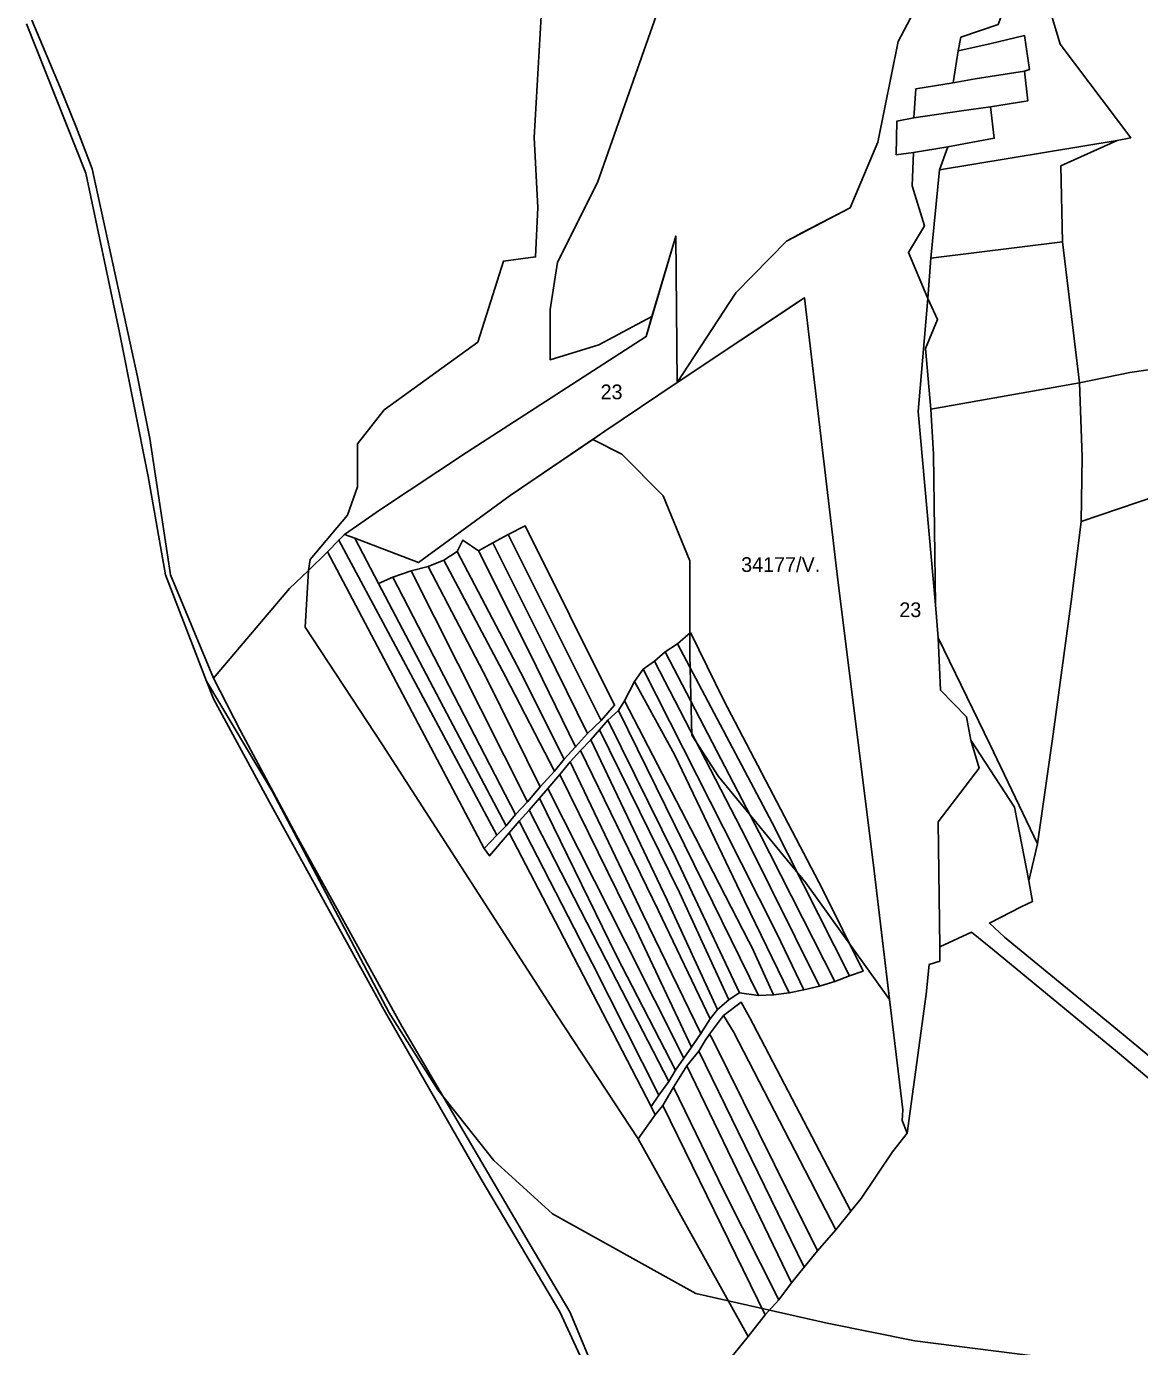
# Model space of a CAD drawing. Extents: x -532083 to -529270, y -1180561 to -1176456.
# Drawn here: x -531324.4 to -530947.6, y -1179426.9 to -1178980.2 of the extents above; entities that cross this region are included whole.
import ezdxf

# ---------------------------------------------------------------- set-up
doc = ezdxf.new("R2010")
doc.units = 0
for name, color, linetype in [('95560013', 7, 'Continuous'), ('95590013', 7, 'Continuous'), ('95610013', 7, 'Continuous'), ('95620013', 7, 'Continuous'), ('95660013', 7, 'Continuous')]:
    doc.layers.add(name, color=color, linetype=linetype)

msp = doc.modelspace()

# ---------------------------------------------------------------- linework, layer by layer
at = {"layer": '95560013'}
for points in [[(-530658.2913, -1178954.87545), (-530725.8063, -1179044.23145), (-530751.3463, -1179049.30845), (-530752.6093, -1179042.71945), (-530853.6623, -1179066.28845), (-530855.4313, -1179080.22645), (-530874.6313, -1179084.02845), (-530909.1583, -1179091.26445), (-530950.9083, -1179097.29245), (-530967.9883, -1179100.78345), (-530973.6643, -1179053.04545), (-530974.3083, -1179027.41445), (-530955.1983, -1179018.79845), (-530950.6093, -1179017.85245), (-530974.5343, -1178986.22345), (-530983.6223, -1178955.52445)], [(-531150.1463, -1178976.77445), (-531152.5333, -1179017.82345), (-531151.3393, -1179041.42645), (-531152.0213, -1179058.18745), (-531162.9583, -1179059.58045), (-531171.5883, -1179086.99245), (-531203.2613, -1179109.97745), (-531212.3343, -1179121.40645), (-531212.3343, -1179136.00945), (-531215.7103, -1179145.53345), (-531228.3693, -1179160.55945), (-531228.8523, -1179164.29845), (-531235.3893, -1179170.37045), (-531261.0553, -1179200.73045), (-531275.5833, -1179165.75645), (-531282.6483, -1179119.64545), (-531286.8093, -1179098.77645), (-531302.1293, -1179028.39245), (-531307.4333, -1179014.46145), (-531313.0023, -1179000.91345), (-531322.5833, -1178978.13445)], [(-530929.8263, -1179340.76445), (-530953.2153, -1179321.37245), (-530993.3103, -1179288.33545), (-530998.4563, -1179283.64445), (-530987.6603, -1179278.10345), (-530983.8933, -1179276.34045), (-530985.1493, -1179269.28745), (-530982.2213, -1179256.82645), (-530976.8443, -1179219.70345), (-530970.5183, -1179173.06145), (-530967.3553, -1179147.74245), (-530884.2313, -1179119.50845)], [(-531116.1203, -1179467.89045), (-531080.0903, -1179423.57845), (-531074.3173, -1179416.15945), (-531069.7743, -1179411.12345), (-531065.4713, -1179405.36745), (-531061.1673, -1179400.09145), (-531056.6253, -1179394.57545), (-531050.4083, -1179387.38045), (-531045.3873, -1179381.14545), (-531041.8013, -1179376.82845), (-531031.2813, -1179360.99945), (-531026.2603, -1179354.76445), (-531019.8023, -1179307.72745), (-531018.8473, -1179297.67245), (-531015.2683, -1179296.47545), (-531015.2793, -1179291.70545), (-531004.4833, -1179286.66745), (-530997.3683, -1179292.40545), (-530955.1243, -1179327.35845), (-530904.5683, -1179369.77645), (-530923.8833, -1179413.83845), (-530953.9483, -1179487.19045)]]:
    msp.add_lwpolyline(points, dxfattribs=at)
for points in [[(-531019.2943, -1179072.28945), (-531025.8403, -1179056.70745), (-531020.4723, -1179047.66145), (-531024.5523, -1179034.09145), (-531024.1223, -1179022.89045), (-531012.5273, -1179020.95245), (-531015.3193, -1179028.70645), (-531018.3253, -1179058.64645)], [(-531018.2783, -1179109.66745), (-531020.0433, -1179089.23245), (-531015.9633, -1179079.32345), (-531019.2943, -1179072.28945), (-531018.3253, -1179058.64645), (-530973.6643, -1179053.04545), (-530967.9883, -1179100.78345)], [(-530884.2313, -1179119.50845), (-530967.3553, -1179147.74245), (-530967.0393, -1179125.84945), (-530967.9883, -1179100.78345), (-530950.9083, -1179097.29245), (-530909.1583, -1179091.26445), (-530874.6313, -1179084.02845), (-530875.3893, -1179085.80245), (-530885.7473, -1179102.27545), (-530860.2313, -1179130.15245), (-530857.4993, -1179133.02145), (-530831.6833, -1179099.23445), (-530851.1363, -1179133.70045), (-530860.4833, -1179136.74145), (-530875.3893, -1179122.80345)], [(-531165.1163, -1179253.85345), (-531194.3713, -1179199.25245), (-531218.6643, -1179153.99845), (-531216.7653, -1179152.09445), (-531213.1783, -1179153.36345), (-531205.1623, -1179168.70445), (-531180.9433, -1179214.88745), (-531161.9993, -1179250.72645)], [(-531169.4333, -1179258.42345), (-531222.4623, -1179158.02045), (-531218.6643, -1179153.99845), (-531194.3713, -1179199.25245), (-531165.1163, -1179253.85345)], [(-531117.2793, -1179356.63845), (-531144.6613, -1179315.17945), (-531203.9123, -1179223.31745), (-531230.0623, -1179183.48645), (-531228.8523, -1179164.29845), (-531222.4623, -1179158.02045), (-531169.4333, -1179258.42345), (-531167.6543, -1179260.89745), (-531160.9723, -1179253.13645), (-531143.9163, -1179285.76645), (-531112.9723, -1179345.70745), (-531111.6153, -1179348.52845)], [(-531116.1203, -1179467.89045), (-531124.8823, -1179452.54945), (-531140.4943, -1179415.15645), (-531154.1953, -1179391.98545), (-531197.3323, -1179318.53245), (-531232.9843, -1179254.01545), (-531251.9673, -1179218.60745), (-531261.0553, -1179200.73045), (-531235.3893, -1179170.37045), (-531228.8523, -1179164.29845), (-531230.0623, -1179183.48645), (-531203.9123, -1179223.31745), (-531144.6613, -1179315.17945), (-531117.2793, -1179356.63845), (-531080.0903, -1179423.57845)], [(-531161.9993, -1179250.72645), (-531180.9433, -1179214.88745), (-531205.1623, -1179168.70445), (-531200.3663, -1179166.54045), (-531158.8823, -1179246.87745)], [(-531079.8783, -1179289.81545), (-531097.8853, -1179254.72745), (-531121.9943, -1179208.45245), (-531118.5393, -1179201.88645), (-531104.9123, -1179226.75245), (-531081.4163, -1179275.87345), (-531066.1913, -1179307.25045), (-531071.4673, -1179307.95545), (-531078.7813, -1179291.95345)], [(-531079.8783, -1179289.81545), (-531078.7813, -1179291.95345), (-531071.4673, -1179307.95545), (-531076.5673, -1179308.13245), (-531092.1063, -1179276.65345), (-531123.9943, -1179211.73545), (-531121.9943, -1179208.45245), (-531097.8853, -1179254.72745)], [(-531083.0753, -1179307.25045), (-531104.6933, -1179261.33545), (-531127.6423, -1179214.90245), (-531123.9943, -1179211.73545), (-531092.1063, -1179276.65345), (-531076.5673, -1179308.13245)], [(-531106.9923, -1179337.23945), (-531128.1893, -1179296.22645), (-531154.1943, -1179245.38045), (-531150.7603, -1179241.40545), (-531124.6753, -1179294.68445), (-531104.7063, -1179333.35845)], [(-531112.9723, -1179345.70745), (-531143.9163, -1179285.76645), (-531160.9723, -1179253.13645), (-531157.6293, -1179249.09145), (-531132.8003, -1179297.41545), (-531110.3343, -1179341.82645)], [(-531056.6253, -1179394.57545), (-531071.2093, -1179365.31645), (-531092.2493, -1179322.62745), (-531093.2053, -1179321.18845), (-531088.4233, -1179314.95345), (-531085.0763, -1179320.46945), (-531050.4083, -1179387.38045)], [(-531065.4713, -1179405.36745), (-531100.8563, -1179331.98045), (-531096.7913, -1179326.94445), (-531061.1673, -1179400.09145)], [(-531069.7743, -1179411.12345), (-531088.1843, -1179374.43045), (-531105.3983, -1179339.17545), (-531100.8563, -1179331.98045), (-531065.4713, -1179405.36745)], [(-531080.0903, -1179423.57845), (-531117.2793, -1179356.63845), (-531111.6153, -1179348.52845), (-531108.9853, -1179345.41145), (-531074.3173, -1179416.15945)]]:
    msp.add_lwpolyline(points, close=True, dxfattribs=at)
at = {"layer": '95590013'}
for points in [[(-530986.5903, -1178995.34045), (-531003.2823, -1178997.94445), (-531010.7013, -1178999.24745), (-531009.0323, -1178988.45645), (-530998.2743, -1178986.03745), (-530986.5903, -1178983.24645), (-530984.9213, -1178994.78145)], [(-530998.0893, -1179007.43345), (-531007.9193, -1179008.73645), (-531024.0553, -1179011.15445), (-531023.3133, -1179001.29345), (-531010.7013, -1178999.24745), (-531003.2823, -1178997.94445), (-530986.5903, -1178995.34045), (-530985.4773, -1179005.38745)], [(-530996.7913, -1179018.03845), (-531012.5273, -1179020.95245), (-531024.1223, -1179022.89045), (-531029.9903, -1179023.62045), (-531029.8043, -1179012.27145), (-531024.0553, -1179011.15445), (-531007.9193, -1179008.73645), (-530998.0893, -1179007.43345)], [(-531134.4233, -1179219.45745), (-531148.5713, -1179190.83345), (-531166.5553, -1179154.99445), (-531161.2803, -1179152.10845), (-531129.8673, -1179215.12745)], [(-531129.8673, -1179215.12745), (-531161.2803, -1179152.10845), (-531155.5253, -1179149.22145), (-531125.3113, -1179209.83545)], [(-531142.3363, -1179228.11645), (-531157.2033, -1179198.77145), (-531178.5453, -1179157.88045), (-531176.6263, -1179154.03245), (-531171.3513, -1179157.64045), (-531154.0863, -1179192.03645), (-531138.5003, -1179224.02745)], [(-531138.5003, -1179224.02745), (-531154.0863, -1179192.03645), (-531171.3513, -1179157.64045), (-531166.5553, -1179154.99445), (-531148.5713, -1179190.83345), (-531134.4233, -1179219.45745)], [(-531150.4893, -1179237.49745), (-531168.4733, -1179201.17645), (-531188.3763, -1179162.93245), (-531183.1013, -1179160.76745), (-531162.2393, -1179200.21445), (-531145.6933, -1179232.20545)], [(-531145.6933, -1179232.20545), (-531162.2393, -1179200.21445), (-531183.1013, -1179160.76745), (-531178.5453, -1179157.88045), (-531157.2033, -1179198.77145), (-531142.3363, -1179228.11645)], [(-531154.8053, -1179242.54845), (-531194.1313, -1179164.37545), (-531188.3763, -1179162.93245), (-531168.4733, -1179201.17645), (-531150.4893, -1179237.49745)], [(-530989.9193, -1179244.35145), (-531004.7343, -1179221.68245), (-531006.2403, -1179213.87345), (-531015.0283, -1179204.80645), (-531015.7483, -1179187.08645), (-530998.3523, -1179223.06645), (-530982.2213, -1179256.82645), (-530985.1493, -1179269.28745)], [(-531080.7573, -1179254.94745), (-531111.8113, -1179194.95445), (-531108.1743, -1179191.85445), (-531076.3653, -1179252.96545), (-531050.7153, -1179303.36945), (-531055.9913, -1179304.95645)], [(-531088.4433, -1179251.42345), (-531115.6303, -1179197.69145), (-531111.8113, -1179194.95445), (-531080.7573, -1179254.94745), (-531055.9913, -1179304.95645), (-531061.2673, -1179306.19145), (-531070.4363, -1179287.10745)], [(-531103.3753, -1179273.23045), (-531130.4163, -1179218.21545), (-531127.6423, -1179214.90245), (-531104.6933, -1179261.33545), (-531083.0753, -1179307.25045), (-531084.1303, -1179307.95545), (-531086.5923, -1179309.54345)], [(-531107.5473, -1179275.87345), (-531133.3223, -1179221.66145), (-531130.4163, -1179218.21545), (-531103.3753, -1179273.23045), (-531086.5923, -1179309.54345), (-531090.4613, -1179312.89545)], [(-531115.6723, -1179280.80745), (-531140.3243, -1179229.08145), (-531136.8893, -1179225.23845), (-531110.4023, -1179279.48545), (-531092.9233, -1179316.07045), (-531096.0893, -1179321.00945)], [(-531117.8683, -1179286.09345), (-531143.8903, -1179233.32245), (-531140.3243, -1179229.08145), (-531115.6723, -1179280.80745), (-531096.0893, -1179321.00945), (-531099.2543, -1179325.59645)], [(-531121.6013, -1179290.05845), (-531147.8533, -1179238.09245), (-531143.8903, -1179233.32245), (-531117.8683, -1179286.09345), (-531099.2543, -1179325.59645), (-531101.8923, -1179329.30145)], [(-531124.6753, -1179294.68445), (-531150.7603, -1179241.40545), (-531147.8533, -1179238.09245), (-531121.6013, -1179290.05845), (-531101.8923, -1179329.30145), (-531104.7063, -1179333.35845)], [(-531132.8003, -1179297.41545), (-531157.6293, -1179249.09145), (-531154.1943, -1179245.38045), (-531128.1893, -1179296.22645), (-531106.9923, -1179337.23945), (-531110.3343, -1179341.82645)], [(-531050.4083, -1179387.38045), (-531085.0763, -1179320.46945), (-531088.4233, -1179314.95345), (-531082.4463, -1179310.39645), (-531079.5773, -1179315.67245), (-531078.3813, -1179317.83145), (-531045.3873, -1179381.14545)], [(-531074.3173, -1179416.15945), (-531108.9853, -1179345.41145), (-531105.3983, -1179339.17545), (-531088.1843, -1179374.43045), (-531069.7743, -1179411.12345)]]:
    msp.add_lwpolyline(points, close=True, dxfattribs=at)
at = {"layer": '95610013'}
for points in [[(-530986.5903, -1178983.24645), (-530998.2743, -1178986.03745), (-531009.0323, -1178988.45645), (-531008.1043, -1178983.80445), (-530995.4923, -1178979.52545), (-530991.7833, -1178969.47845), (-530986.2193, -1178966.50145), (-530988.6303, -1178960.91945), (-530990.8563, -1178955.71045), (-530986.5903, -1178955.52445), (-530983.6223, -1178955.52445), (-530974.5343, -1178986.22345), (-530950.6093, -1179017.85245), (-530955.1983, -1179018.79845), (-531015.3193, -1179028.70645), (-531012.5273, -1179020.95245), (-530996.7913, -1179018.03845), (-530998.0893, -1179007.43345), (-530985.4773, -1179005.38745), (-530986.5903, -1178995.34045), (-530984.9213, -1178994.78145)], [(-530973.6643, -1179053.04545), (-531018.3253, -1179058.64645), (-531015.3193, -1179028.70645), (-530955.1983, -1179018.79845), (-530974.3083, -1179027.41445)], [(-531158.8823, -1179246.87745), (-531200.3663, -1179166.54045), (-531194.1313, -1179164.37545), (-531154.8053, -1179242.54845)], [(-531071.9733, -1179249.66145), (-531103.9923, -1179189.11845), (-531099.6283, -1179185.28745), (-531088.3533, -1179208.27045), (-531054.9363, -1179272.14445), (-531041.2183, -1179299.84045), (-531045.7913, -1179301.42845)], [(-531076.3653, -1179252.96545), (-531108.1743, -1179191.85445), (-531103.9923, -1179189.11845), (-531071.9733, -1179249.66145), (-531045.7913, -1179301.42845), (-531050.7153, -1179303.36945)], [(-531081.4163, -1179275.87345), (-531104.9123, -1179226.75245), (-531118.5393, -1179201.88645), (-531115.6303, -1179197.69145), (-531088.4433, -1179251.42345), (-531070.4363, -1179287.10745), (-531061.2673, -1179306.19145), (-531066.1913, -1179307.25045)], [(-531110.4023, -1179279.48545), (-531136.8893, -1179225.23845), (-531133.3223, -1179221.66145), (-531107.5473, -1179275.87345), (-531090.4613, -1179312.89545), (-531092.9233, -1179316.07045)], [(-531061.1673, -1179400.09145), (-531096.7913, -1179326.94445), (-531094.6393, -1179323.34745), (-531093.2053, -1179321.18845), (-531092.2493, -1179322.62745), (-531071.2093, -1179365.31645), (-531056.6253, -1179394.57545)]]:
    msp.add_lwpolyline(points, close=True, dxfattribs=at)
at = {"layer": '95620013'}
msp.add_lwpolyline([(-530995.4923, -1178979.52545), (-531008.1043, -1178983.80445), (-531009.0323, -1178988.45645), (-531010.7013, -1178999.24745), (-531023.3133, -1179001.29345), (-531024.0553, -1179011.15445), (-531029.8043, -1179012.27145), (-531029.9903, -1179023.62045), (-531024.1223, -1179022.89045), (-531024.5523, -1179034.09145), (-531020.4723, -1179047.66145), (-531025.8403, -1179056.70745), (-531019.2943, -1179072.28945), (-531015.9633, -1179079.32345), (-531020.0433, -1179089.23245), (-531018.2783, -1179109.66745), (-531017.3293, -1179124.89745), (-531016.6973, -1179175.98045), (-531015.7483, -1179187.08645), (-531015.0283, -1179204.80645), (-531006.2403, -1179213.87345), (-531004.7343, -1179221.68245), (-531001.9723, -1179231.25345), (-531015.7823, -1179249.38945), (-531015.2793, -1179291.70545), (-531015.2683, -1179296.47545), (-531018.8473, -1179297.67245), (-531019.8023, -1179307.72745), (-531026.2603, -1179354.76445), (-531027.9343, -1179350.44745), (-531027.6953, -1179346.85045), (-531031.5953, -1179315.04845), (-531037.8153, -1179263.12745), (-531049.4773, -1179169.35045), (-531061.0463, -1179072.00045), (-531104.0743, -1179100.66545), (-531084.2413, -1179070.40245), (-531067.1513, -1179052.83645), (-531045.6303, -1179041.61945), (-531036.2273, -1179019.31245), (-531029.3253, -1178985.34245), (-531009.6953, -1178948.12645)], dxfattribs=at)
msp.add_lwpolyline([(-531128.5713, -1179117.17345), (-531160.6413, -1179138.97245), (-531191.6573, -1179161.61745), (-531213.1783, -1179153.36345), (-531216.7653, -1179152.09445), (-531204.5273, -1179143.62845), (-531175.4113, -1179124.36945), (-531114.6723, -1179085.13745), (-531104.6033, -1179051.12945), (-531104.0743, -1179100.66545)], close=True, dxfattribs=at)
at = {"layer": '95660013'}
for points in [[(-531009.6953, -1178948.12645), (-531029.3253, -1178985.34245), (-531036.2273, -1179019.31245), (-531045.6303, -1179041.61945), (-531062.1193, -1179050.21345), (-531065.2463, -1179051.84345), (-531067.1513, -1179052.83645), (-531084.2413, -1179070.40245), (-531104.0743, -1179100.66545), (-531104.6033, -1179051.12945), (-531112.6673, -1179078.36445), (-531130.6253, -1179088.00045), (-531147.1253, -1179093.00045), (-531147.1253, -1179076.00045), (-531144.6253, -1179060.00045), (-531131.1253, -1179033.00045), (-531104.0003, -1178956.00045)], [(-530995.4923, -1178979.52545), (-531008.1043, -1178983.80445), (-531009.0323, -1178988.45645), (-531010.7013, -1178999.24745), (-531023.3133, -1179001.29345), (-531024.0553, -1179011.15445), (-531029.8043, -1179012.27145), (-531029.9903, -1179023.62045), (-531024.1223, -1179022.89045), (-531024.5523, -1179034.09145), (-531020.4723, -1179047.66145), (-531025.8403, -1179056.70745), (-531019.2943, -1179072.28945), (-531022.6063, -1179110.49345), (-531016.6973, -1179175.98045), (-531015.7483, -1179187.08645), (-531015.0283, -1179204.80645), (-531006.2403, -1179213.87345), (-531004.7343, -1179221.68245), (-531001.9723, -1179231.25345), (-531015.7823, -1179249.38945), (-531015.2793, -1179291.70545), (-531015.2683, -1179296.47545), (-531018.8473, -1179297.67245), (-531019.8023, -1179307.72745), (-531026.2603, -1179354.76445), (-531027.9343, -1179350.44745), (-531027.6953, -1179346.85045), (-531031.5953, -1179315.04845), (-531032.2553, -1179309.53945), (-531037.8153, -1179263.12745), (-531049.4773, -1179169.35045), (-531061.0463, -1179072.00045), (-531063.5033, -1179073.63745), (-531066.5503, -1179075.66745), (-531104.0743, -1179100.66545), (-531084.2413, -1179070.40245), (-531067.1513, -1179052.83645), (-531065.2463, -1179051.84345), (-531062.1193, -1179050.21345), (-531045.6303, -1179041.61945), (-531036.2273, -1179019.31245), (-531029.3253, -1178985.34245), (-531009.6953, -1178948.12645)], [(-531104.0003, -1178956.00045), (-531131.1253, -1179033.00045), (-531144.6253, -1179060.00045), (-531147.1253, -1179076.00045), (-531147.1253, -1179093.00045), (-531130.6253, -1179088.00045), (-531112.6673, -1179078.36445), (-531114.6723, -1179085.13745), (-531175.4113, -1179124.36945), (-531204.5273, -1179143.62845), (-531216.7653, -1179152.09445), (-531213.1783, -1179153.36345), (-531191.6573, -1179161.61745), (-531160.6413, -1179138.97245), (-531132.7033, -1179119.98245), (-531122.8753, -1179125.00045), (-531108.8753, -1179139.00045), (-531099.8753, -1179161.00045), (-531099.8753, -1179193.00045), (-531099.1253, -1179220.00045), (-531090.1253, -1179234.00045), (-531060.6253, -1179270.00045), (-531032.2553, -1179309.53945), (-531031.5953, -1179315.04845), (-531027.6953, -1179346.85045), (-531027.9343, -1179350.44745), (-531026.2603, -1179354.76445), (-531019.8023, -1179307.72745), (-531018.8473, -1179297.67245), (-531015.2683, -1179296.47545), (-531015.2793, -1179291.70545), (-531015.7823, -1179249.38945), (-531001.9723, -1179231.25345), (-531004.7343, -1179221.68245), (-531006.2403, -1179213.87345), (-531015.0283, -1179204.80645), (-531015.7483, -1179187.08645), (-531016.6973, -1179175.98045), (-531022.6063, -1179110.49345), (-531019.2943, -1179072.28945), (-531025.8403, -1179056.70745), (-531020.4723, -1179047.66145), (-531024.5523, -1179034.09145), (-531024.1223, -1179022.89045), (-531029.9903, -1179023.62045), (-531029.8043, -1179012.27145), (-531024.0553, -1179011.15445), (-531023.3133, -1179001.29345), (-531010.7013, -1178999.24745), (-531009.0323, -1178988.45645), (-531008.1043, -1178983.80445), (-530995.4923, -1178979.52545)], [(-530976.6873, -1179431.00045), (-531023.6873, -1179425.00045), (-531053.3123, -1179419.00045), (-531097.8123, -1179409.00045), (-531146.3753, -1179382.00045), (-531166.1873, -1179364.00045), (-531185.1253, -1179340.00045), (-531201.6253, -1179314.00045), (-531241.1873, -1179239.00045), (-531263.3953, -1179201.80545), (-531277.2813, -1179165.72345), (-531283.1133, -1179132.47845), (-531292.8583, -1179083.76045), (-531304.2533, -1179029.90345), (-531324.3793, -1178979.33545)], [(-531126.8743, -1179451.88045), (-531143.7973, -1179415.14145), (-531170.5143, -1179370.32245), (-531203.2523, -1179313.10545), (-531242.0643, -1179242.68445), (-531261.1083, -1179207.74645), (-531263.3953, -1179201.80545), (-531241.1873, -1179239.00045), (-531201.6253, -1179314.00045), (-531185.1253, -1179340.00045), (-531166.1873, -1179364.00045), (-531146.3753, -1179382.00045), (-531097.8123, -1179409.00045), (-531053.3123, -1179419.00045), (-531023.6873, -1179425.00045), (-530976.6873, -1179431.00045)]]:
    msp.add_lwpolyline(points, dxfattribs=at)
for points in [[(-531104.0743, -1179100.66545), (-531128.5713, -1179117.17345), (-531132.7033, -1179119.98245), (-531160.6413, -1179138.97245), (-531191.6573, -1179161.61745), (-531213.1783, -1179153.36345), (-531216.7653, -1179152.09445), (-531204.5273, -1179143.62845), (-531175.4113, -1179124.36945), (-531114.6723, -1179085.13745), (-531112.6673, -1179078.36445), (-531104.6033, -1179051.12945)], [(-531032.2553, -1179309.53945), (-531060.6253, -1179270.00045), (-531090.1253, -1179234.00045), (-531099.1253, -1179220.00045), (-531099.8753, -1179193.00045), (-531099.8753, -1179161.00045), (-531108.8753, -1179139.00045), (-531122.8753, -1179125.00045), (-531132.7033, -1179119.98245), (-531128.5713, -1179117.17345), (-531104.0743, -1179100.66545), (-531066.5503, -1179075.66745), (-531063.5033, -1179073.63745), (-531061.0463, -1179072.00045), (-531049.4773, -1179169.35045), (-531037.8153, -1179263.12745)]]:
    msp.add_lwpolyline(points, close=True, dxfattribs=at)

# ---------------------------------------------------------------- texts
for rotation, p in [(0, (-531130.04728, -1179106.37345)), (0.0000001, (-531028.9388, -1179180.10007))]:
    msp.add_text('23', height=5, rotation=rotation, dxfattribs=at).set_placement(p)
msp.add_text('34177/V.', height=5, dxfattribs=at).set_placement((-531082.4793, -1179164.80515))

doc.saveas('drawing.dxf')
